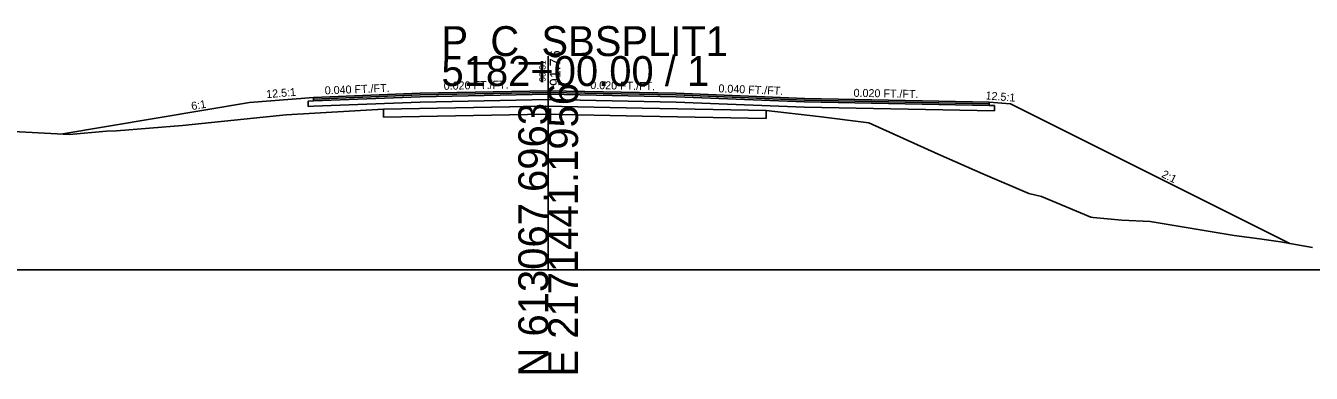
# Model space of a CAD drawing. Extents: x -26 to 1303, y -3010 to 12023.
# Drawn here: x 101 to 221.5, y 5490.3 to 5522.8 of the extents above; entities that cross this region are included whole.
import ezdxf

# ---------------------------------------------------------------- set-up
doc = ezdxf.new("R2010")
doc.units = 0
for name, color, linetype in [('RD_GPK_XS_Cell', 7, 'Continuous'), ('RD_XS_Base', 7, 'Continuous'), ('RD_XS_ExGround', 7, 'Continuous'), ('RD_XS_ExPaveRet', 7, 'Continuous'), ('RD_XS_Greenside', 7, 'Continuous'), ('RD_XS_Pave', 7, 'Continuous'), ('RD_XS_PaveOvlay_CP', 7, 'Continuous'), ('RD_XS_TieSlope', 7, 'Continuous'), ('RD_XS_TX_Elev_EX', 7, 'Continuous'), ('RD_XS_TX_Elev_PR', 7, 'Continuous'), ('RD_XS_TX_ShdSlope', 7, 'Continuous'), ('RD_XS_TX_Slope', 7, 'Continuous')]:
    doc.layers.add(name, color=color, linetype=linetype)

msp = doc.modelspace()

# ---------------------------------------------------------------- linework, layer by layer
at = {"layer": 'RD_GPK_XS_Cell'}
for p, q in [((150, 5500), (150, 5520)), ((0, 5500), (150, 5500)), ((150, 5500), (300, 5500))]:
    msp.add_line(p, q, dxfattribs=at)
at = {"layer": 'RD_XS_Base'}
for p, q in [((127.5, 5515.78), (128, 5515.8)), ((127.5, 5515.28), (127.5, 5515.78)), ((127.5, 5515.78), (127.5, 5515.78)), ((128, 5515.8), (138, 5516.2)), ((128, 5515.8), (128, 5515.8)), ((138, 5515.7), (128, 5515.3)), ((138, 5516.2), (150, 5516.44)), ((150, 5515.94), (138, 5515.7)), ((150, 5516.44), (150, 5516.6)), ((150, 5516.6), (150, 5515.94)), ((150, 5516.44), (150, 5516.44)), ((162, 5516.2), (150, 5516.44)), ((150, 5516.44), (150, 5516.44)), ((150, 5516.44), (150, 5515.94)), ((150, 5515.94), (150, 5515.94)), ((150, 5515.94), (162, 5515.7)), ((150, 5515.94), (150, 5515.94)), ((174, 5515.72), (162, 5516.2)), ((162, 5516.2), (162, 5516.2)), ((162, 5515.7), (162, 5515.7)), ((162, 5515.7), (174, 5515.22)), ((191.32, 5515.37), (174, 5515.72)), ((174, 5515.72), (174, 5515.72)), ((128, 5515.3), (127.5, 5515.28)), ((127.5, 5515.28), (127.5, 5515.28)), ((127.5, 5515.28), (127.5, 5515.28)), ((128, 5515.3), (128, 5515.3)), ((174, 5515.22), (174, 5515.22)), ((174, 5515.22), (191.82, 5514.86)), ((191.82, 5515.36), (191.32, 5515.37)), ((191.32, 5515.37), (191.32, 5515.37)), ((191.82, 5514.86), (191.82, 5515.36)), ((191.82, 5515.36), (191.82, 5515.36)), ((191.82, 5514.86), (191.82, 5514.86)), ((191.82, 5514.86), (191.82, 5514.86))]:
    msp.add_line(p, q, dxfattribs=at)
at = {"layer": 'RD_XS_ExGround'}
msp.add_lwpolyline([(98.73, 5512.99), (105.14, 5512.65), (108.62, 5512.96), (109.55, 5513), (115.74, 5513.5), (123.3, 5514.28), (125.44, 5514.5), (134.57, 5515.04), (134.58, 5515.04), (134.58, 5515.04), (134.58, 5515.04), (134.58, 5515.04), (149.77, 5515.32), (158.81, 5515.14), (170.43, 5514.9), (175.34, 5514.36), (180.04, 5513.75), (186.54, 5510.82), (190.72, 5508.97), (195.04, 5507.14), (196.22, 5506.84), (200.85, 5504.91), (201.05, 5504.9), (203.74, 5504.65), (206.4, 5504.52), (214.28, 5503.21), (216.65, 5502.9), (218.61, 5502.6), (221.62, 5502.09)], dxfattribs=at)
at = {"layer": 'RD_XS_ExPaveRet'}
for p, q in [((134.58, 5515.04), (134.58, 5514.29)), ((170.43, 5514.15), (170.43, 5514.9))]:
    msp.add_line(p, q, dxfattribs=at)
for points in [[(170.43, 5514.9), (158.81, 5515.14), (149.78, 5515.32), (149.77, 5515.32), (149.76, 5515.32), (134.58, 5515.04)], [(170.43, 5514.9), (158.81, 5515.14), (149.78, 5515.32), (149.77, 5515.32), (149.76, 5515.32), (134.58, 5515.04)], [(134.58, 5514.29), (134.58, 5515.04)], [(134.58, 5514.29), (149.76, 5514.57), (149.77, 5514.57), (149.78, 5514.57), (158.81, 5514.39), (170.43, 5514.15)], [(134.58, 5514.29), (149.76, 5514.57), (149.77, 5514.57), (149.78, 5514.57), (158.81, 5514.39), (170.43, 5514.15)], [(170.43, 5514.15), (170.43, 5514.9)]]:
    msp.add_lwpolyline(points, dxfattribs=at)
at = {"layer": 'RD_XS_Greenside'}
for p, q in [((122, 5515.64), (104.33, 5512.69)), ((193.32, 5515.53), (219.48, 5502.45))]:
    msp.add_line(p, q, dxfattribs=at)
at = {"layer": 'RD_XS_Pave'}
for p, q in [((150, 5516.76), (138, 5516.52)), ((162, 5516.52), (150, 5516.76)), ((138, 5516.52), (128, 5516.12)), ((138, 5516.36), (128, 5515.96)), ((128, 5515.96), (138, 5516.36)), ((128, 5515.8), (138, 5516.2)), ((128, 5516.12), (128, 5516.12)), ((128, 5516.12), (128, 5515.96)), ((128, 5515.96), (128, 5515.96)), ((128, 5515.96), (128, 5515.8)), ((128, 5515.96), (128, 5515.96)), ((128, 5515.96), (128, 5515.96)), ((128, 5515.8), (128, 5515.8)), ((128, 5515.8), (128, 5515.8)), ((150, 5516.6), (138, 5516.36)), ((138, 5516.36), (150, 5516.6)), ((138, 5516.2), (150, 5516.44)), ((150, 5516.44), (150, 5516.6)), ((150, 5516.6), (162, 5516.36)), ((162, 5516.36), (150, 5516.6)), ((150, 5516.6), (150, 5516.6)), ((150, 5516.6), (150, 5516.44)), ((150, 5516.44), (150, 5516.44)), ((150, 5516.44), (150, 5516.44)), ((150, 5516.44), (150, 5516.44)), ((150, 5516.44), (162, 5516.2)), ((174, 5516.04), (162, 5516.52)), ((162, 5516.52), (162, 5516.52)), ((162, 5516.36), (162, 5516.36)), ((162, 5516.36), (174, 5515.88)), ((174, 5515.88), (162, 5516.36)), ((162, 5516.36), (162, 5516.36)), ((162, 5516.2), (162, 5516.2)), ((162, 5516.2), (174, 5515.72)), ((191.32, 5515.69), (174, 5516.04)), ((174, 5516.04), (174, 5516.04)), ((174, 5515.88), (174, 5515.88)), ((174, 5515.88), (191.32, 5515.53)), ((191.32, 5515.53), (174, 5515.88)), ((174, 5515.88), (174, 5515.88)), ((174, 5515.72), (174, 5515.72)), ((174, 5515.72), (191.32, 5515.37)), ((191.32, 5515.53), (191.32, 5515.69)), ((191.32, 5515.69), (191.32, 5515.69)), ((191.32, 5515.53), (191.32, 5515.53)), ((191.32, 5515.53), (191.32, 5515.53)), ((191.32, 5515.37), (191.32, 5515.53)), ((191.32, 5515.53), (191.32, 5515.53)), ((191.32, 5515.37), (191.32, 5515.37)), ((191.32, 5515.37), (191.32, 5515.37))]:
    msp.add_line(p, q, dxfattribs=at)
at = {"layer": 'RD_XS_PaveOvlay_CP'}
for p, q in [((150, 5516.76), (138, 5516.52)), ((162, 5516.52), (150, 5516.76)), ((138, 5516.52), (128, 5516.12)), ((128, 5516.12), (128, 5516.12)), ((174, 5516.04), (162, 5516.52)), ((162, 5516.52), (162, 5516.52)), ((191.32, 5515.69), (174, 5516.04)), ((174, 5516.04), (174, 5516.04)), ((191.32, 5515.69), (191.32, 5515.69))]:
    msp.add_line(p, q, dxfattribs=at)
at = {"layer": 'RD_XS_TieSlope'}
for p, q in [((128, 5516.12), (122, 5515.64)), ((191.32, 5515.69), (193.32, 5515.53))]:
    msp.add_line(p, q, dxfattribs=at)

# ---------------------------------------------------------------- texts
at = {"layer": 'RD_GPK_XS_Cell'}
for s, p in [('P_C_SBSPLIT1', (140, 5520)), ('5182+00.00 / 1', (140, 5517.2))]:
    msp.add_text(s, height=2.8, dxfattribs=at).set_placement(p)
for s, p in [('E 2171441.1956', (152.8, 5490)), ('N 613067.6963', (150, 5490))]:
    msp.add_text(s, height=2.8, rotation=90, dxfattribs=at).set_placement(p)
at = {"layer": 'RD_XS_TX_Elev_EX'}
msp.add_text('90.31', height=0.6, rotation=90, dxfattribs=at).set_placement((149.76, 5517.6))
at = {"layer": 'RD_XS_TX_Elev_PR'}
msp.add_text('91.76', height=1, rotation=90, dxfattribs=at).set_placement((151.15, 5517.19))
at = {"layer": 'RD_XS_TX_ShdSlope'}
for rotation, p in [(4.5739, (123.61, 5516.06)), (355.4261, (190.96, 5515.95))]:
    msp.add_text('12.5:1', height=0.75, rotation=rotation, dxfattribs=at).set_placement(p)
at = {"layer": 'RD_XS_TX_Slope'}
for s, rotation, p in [('0.040 FT./FT.', 2.2906, (129.08, 5516.41)), ('0.020 FT./FT.', 1.1458, (140.22, 5516.84)), ('0.020 FT./FT.', 358.8542, (153.94, 5516.92)), ('0.040 FT./FT.', 357.7094, (165.94, 5516.61)), ('0.020 FT./FT.', 358.8542, (178.61, 5516.19)), ('6:1', 9.4623, (116.62, 5514.94)), ('2:1', 333.4349, (207.4, 5508.7))]:
    msp.add_text(s, height=0.75, rotation=rotation, dxfattribs=at).set_placement(p)

doc.saveas('drawing.dxf')
